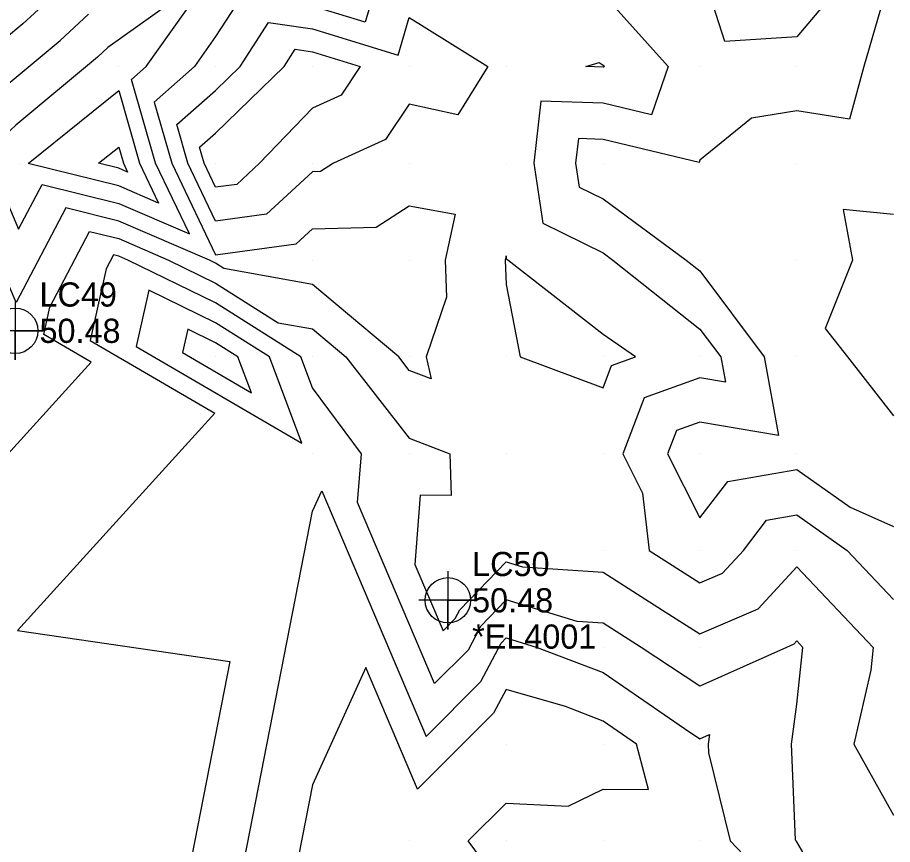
# Model space of a CAD drawing. Extents: x 2188792 to 2191981, y 386090 to 389710.
# Drawn here: x 2190119.7 to 2190210, y 387449.8 to 387535.2 of the extents above; entities that cross this region are included whole.
import ezdxf

# ---------------------------------------------------------------- set-up
doc = ezdxf.new("R2010")
doc.units = 0
for name, color, linetype in [('DTM Contours Major', 7, 'Continuous'), ('DTM Contours Minor', 7, 'Continuous'), ('Exist DTM QL2 LIDAR Elevation Point', 7, 'Continuous'), ('Exist DTM Regular Point Underwater CELL', 7, 'Continuous'), ('Exist DTM Regular Point Underwater Cogo Comment', 7, 'Continuous'), ('Exist DTM Regular Point Underwater Cogo Elevation', 7, 'Continuous'), ('Exist DTM Regular Point Underwater Cogo Number', 7, 'Continuous')]:
    doc.layers.add(name, color=color, linetype=linetype)

msp = doc.modelspace()

# ---------------------------------------------------------------- linework, layer by layer
at = {"layer": 'DTM Contours Major'}
for points in [[(2190120.784, 387520.144), (2190130.12, 387527.661), (2190132.267, 387520.154), (2190134.229, 387516.045), (2190130.12, 387517.817), (2190120.784, 387520.144)], [(2190210.127, 387514.854), (2190204.91, 387515.37), (2190205.884, 387510.153), (2190203.049, 387503.074), (2190205.351, 387500.152), (2190210.127, 387494.072)], [(2190140.121, 387503.672), (2190133.237, 387507.036), (2190131.936, 387501.22), (2190149.032, 387491.241), (2190145.675, 387500.152), (2190140.121, 387503.672)], [(2190141.057, 387437.7), (2190150.122, 387484.226), (2190151.078, 387486.326), (2190161.854, 387460.951), (2190167.508, 387466.609), (2190169.599, 387470.573)], [(2190169.599, 387470.573), (2190170.124, 387471.118), (2190173.327, 387470.149), (2190180.125, 387467.535), (2190188.52, 387461.754), (2190190.126, 387460.694), (2190191.113, 387461.136), (2190190.987, 387460.148), (2190191.023, 387459.251), (2190193.242, 387450.147), (2190200.127, 387442.935)]]:
    msp.add_lwpolyline(points, dxfattribs=at)
at = {"layer": 'DTM Contours Minor'}
for points in [[(2190157.179, 387540.156), (2190155.555, 387534.723), (2190150.122, 387536.394)], [(2190205.968, 387540.156), (2190200.127, 387533.215), (2190192.709, 387532.738), (2190190.326, 387540.156)], [(2190137.419, 387512.855), (2190133.935, 387520.154), (2190131.456, 387528.819), (2190132.964, 387530.155), (2190139.84, 387539.876), (2190128.988, 387532.121), (2190127.921, 387531.132), (2190119.493, 387524.101), (2190117.957, 387522.653), (2190117.61, 387520.473), (2190117.263, 387519.247), (2190119.789, 387513.362), (2190122.207, 387517.975), (2190130.12, 387516.003), (2190137.419, 387512.855)], [(2190209.867, 387539.896), (2190207.05, 387530.155), (2190205.562, 387524.719), (2190200.127, 387525.571), (2190195.461, 387524.82), (2190190.126, 387520.479), (2190190.042, 387520.238), (2190180.125, 387522.611), (2190177.575, 387522.703), (2190177.29, 387520.154), (2190177.666, 387517.695), (2190180.125, 387516.481), (2190188.704, 387510.153), (2190190.126, 387509.028), (2190196.764, 387500.152), (2190198.237, 387492.041), (2190190.126, 387493.426), (2190187.712, 387492.565), (2190186.79, 387490.151), (2190190.126, 387483.515), (2190193.006, 387487.271), (2190200.127, 387488.529), (2190205.652, 387484.625), (2190210.127, 387482.617)], [(2190125.03, 387538.995), (2190120.233, 387534.548), (2190118.327, 387532.958)], [(2190142.832, 387537.445), (2190140.121, 387533.244), (2190137.936, 387530.155), (2190133.791, 387526.483), (2190135.602, 387520.154), (2190140.121, 387510.688), (2190148.449, 387511.826), (2190150.122, 387513.372), (2190156.714, 387513.561), (2190160.123, 387515.743), (2190164.852, 387514.882), (2190163.811, 387510.153), (2190163.953, 387506.323), (2190161.854, 387500.152), (2190162.382, 387497.893), (2190160.123, 387498.751), (2190159.029, 387500.152), (2190150.122, 387507.648), (2190140.979, 387509.294), (2190140.121, 387509.839), (2190139.477, 387510.153), (2190130.12, 387514.189)], [(2190180.125, 387537.656), (2190186.856, 387530.155), (2190185.125, 387525.155), (2190180.125, 387526.351), (2190173.695, 387526.583), (2190172.976, 387520.154), (2190173.923, 387513.952), (2190180.125, 387510.891), (2190181.125, 387510.153), (2190190.126, 387503.025), (2190192.274, 387500.152), (2190192.751, 387497.527), (2190190.126, 387497.975), (2190184.359, 387495.918), (2190182.156, 387490.151), (2190184.21, 387486.066), (2190184.871, 387480.15), (2190190.126, 387476.811), (2190192.459, 387477.817), (2190194.614, 387480.15), (2190197.006, 387483.271), (2190200.127, 387483.822), (2190205.324, 387480.15), (2190210.127, 387475.104)], [(2190130.12, 387514.189), (2190124.661, 387515.549), (2190119.538, 387505.774), (2190114.185, 387518.245), (2190114.921, 387520.842), (2190115.656, 387525.462), (2190118.91, 387528.529), (2190124.077, 387532.84), (2190127.009, 387535.558)], [(2190137.27, 387520.154), (2190136.127, 387524.148), (2190140.121, 387527.686), (2190142.663, 387530.155), (2190145.589, 387534.688), (2190150.122, 387534.035), (2190158.962, 387531.315), (2190160.123, 387535.196), (2190168.231, 387530.155), (2190165.134, 387525.144), (2190160.123, 387526.252), (2190157.678, 387522.599), (2190152.287, 387520.154), (2190150.967, 387519.309), (2190150.122, 387519.285), (2190145.376, 387514.899), (2190140.121, 387514.181), (2190137.27, 387520.154)], [(2190138.937, 387520.154), (2190138.463, 387521.812), (2190140.121, 387523.281), (2190147.199, 387530.155), (2190148.345, 387531.932), (2190150.122, 387531.676), (2190155.065, 387530.155), (2190153.083, 387527.194), (2190150.122, 387525.851), (2190144.664, 387520.154), (2190142.303, 387517.972), (2190140.121, 387517.674), (2190138.937, 387520.154)], [(2190180.125, 387530.091), (2190178.363, 387530.155), (2190179.723, 387530.556), (2190180.125, 387530.28), (2190180.237, 387530.155), (2190180.208, 387530.071), (2190180.125, 387530.091)], [(2190128.032, 387520.152), (2190130.12, 387521.833), (2190130.6, 387520.154), (2190131.039, 387519.235), (2190130.12, 387519.632), (2190128.032, 387520.152)], [(2190102.656, 387472.478), (2190127.28, 387499.605), (2190122.378, 387502.466), (2190123.009, 387505.29), (2190127.115, 387513.123), (2190130.12, 387512.375), (2190135.271, 387510.153), (2190140.121, 387507.783), (2190146.592, 387503.682), (2190150.122, 387503.046), (2190153.561, 387500.152), (2190160.123, 387491.742), (2190164.315, 387490.151), (2190164.443, 387485.831), (2190161.246, 387485.884), (2190160.692, 387478.707), (2190163.602, 387471.856), (2190164.87, 387473.125), (2190165.339, 387474.015), (2190170.124, 387478.977), (2190171.805, 387478.469), (2190180.125, 387477.909), (2190186.275, 387474), (2190190.126, 387471.553), (2190196.133, 387474.143), (2190200.127, 387478.467), (2190208.01, 387470.149), (2190207.754, 387467.776), (2190206.02, 387460.148), (2190210.127, 387452.803)], [(2190205.919, 387440.147), (2190200.127, 387450.048), (2190200.031, 387450.147), (2190200.001, 387450.273), (2190199.597, 387460.148), (2190200.127, 387464.29), (2190200.757, 387470.149), (2190200.127, 387470.815), (2190199.807, 387470.469), (2190199.065, 387470.149), (2190190.126, 387466.15), (2190184.067, 387470.149), (2190180.125, 387472.655), (2190177.438, 387472.836), (2190170.124, 387475.048), (2190167.469, 387472.294), (2190166.189, 387469.867), (2190162.728, 387466.404), (2190154.788, 387485.099), (2190155.178, 387490.151), (2190150.122, 387496.958), (2190148.919, 387500.152), (2190140.121, 387505.728), (2190131.064, 387510.153), (2190130.12, 387510.56), (2190129.569, 387510.698), (2190128.816, 387509.261), (2190127.157, 387501.843), (2190140.037, 387494.325), (2190119.677, 387471.895), (2190141.586, 387468.701), (2190135.24, 387436.13)], [(2190181.006, 387499.27), (2190183.477, 387500.152), (2190180.125, 387502.478), (2190170.294, 387510.153), (2190170.18, 387510.209), (2190170.124, 387510.577), (2190170.03, 387510.153), (2190170.124, 387507.632), (2190171.571, 387500.152), (2190180.125, 387496.962), (2190181.006, 387499.27)], [(2190140.121, 387501.617), (2190137.257, 387503.016), (2190136.716, 387500.596), (2190143.828, 387496.445), (2190142.432, 387500.152), (2190140.121, 387501.617)], [(2190160.98, 387455.499), (2190155.643, 387468.068), (2190150.122, 387455.943), (2190146.873, 387439.27)], [(2190170.124, 387444.852), (2190166.204, 387450.147), (2190170.124, 387454.063), (2190176.528, 387453.744), (2190180.125, 387455.507), (2190184.816, 387455.457), (2190183.594, 387460.148), (2190180.125, 387462.537), (2190176.243, 387464.03), (2190170.124, 387465.81), (2190168.827, 387463.351), (2190160.98, 387455.499)]]:
    msp.add_lwpolyline(points, dxfattribs=at)
at = {"layer": 'Exist DTM QL2 LIDAR Elevation Point'}
for p, q in [((2190130.12, 387530.155), (2190130.12, 387530.155)), ((2190140.121, 387530.155), (2190140.121, 387530.155)), ((2190150.122, 387530.155), (2190150.122, 387530.155)), ((2190160.123, 387530.155), (2190160.123, 387530.155)), ((2190170.124, 387530.155), (2190170.124, 387530.155)), ((2190180.125, 387530.155), (2190180.125, 387530.155)), ((2190190.126, 387530.155), (2190190.126, 387530.155)), ((2190200.127, 387530.155), (2190200.127, 387530.155)), ((2190120.013, 387520.143), (2190120.013, 387520.143)), ((2190130.12, 387520.154), (2190130.12, 387520.154)), ((2190140.121, 387520.154), (2190140.121, 387520.154)), ((2190150.122, 387520.154), (2190150.122, 387520.154)), ((2190160.123, 387520.154), (2190160.123, 387520.154)), ((2190170.124, 387520.154), (2190170.124, 387520.154)), ((2190180.125, 387520.154), (2190180.125, 387520.154)), ((2190190.126, 387520.154), (2190190.126, 387520.154)), ((2190200.127, 387520.154), (2190200.127, 387520.154)), ((2190130.12, 387510.153), (2190130.12, 387510.153)), ((2190140.121, 387510.153), (2190140.121, 387510.153)), ((2190150.122, 387510.153), (2190150.122, 387510.153)), ((2190160.123, 387510.153), (2190160.123, 387510.153)), ((2190170.124, 387510.153), (2190170.124, 387510.153)), ((2190180.125, 387510.153), (2190180.125, 387510.153)), ((2190190.126, 387510.153), (2190190.126, 387510.153)), ((2190200.127, 387510.153), (2190200.127, 387510.153)), ((2190140.121, 387500.152), (2190140.121, 387500.152)), ((2190150.122, 387500.152), (2190150.122, 387500.152)), ((2190160.123, 387500.152), (2190160.123, 387500.152)), ((2190170.124, 387500.152), (2190170.124, 387500.152)), ((2190180.125, 387500.152), (2190180.125, 387500.152)), ((2190190.126, 387500.152), (2190190.126, 387500.152)), ((2190200.127, 387500.152), (2190200.127, 387500.152)), ((2190150.122, 387490.151), (2190150.122, 387490.151)), ((2190160.123, 387490.151), (2190160.123, 387490.151)), ((2190170.124, 387490.151), (2190170.124, 387490.151)), ((2190180.125, 387490.151), (2190180.125, 387490.151)), ((2190190.126, 387490.151), (2190190.126, 387490.151)), ((2190200.127, 387490.151), (2190200.127, 387490.151)), ((2190170.124, 387480.15), (2190170.124, 387480.15)), ((2190180.125, 387480.15), (2190180.125, 387480.15)), ((2190190.126, 387480.15), (2190190.126, 387480.15)), ((2190200.127, 387480.15), (2190200.127, 387480.15)), ((2190170.124, 387470.149), (2190170.124, 387470.149)), ((2190180.125, 387470.149), (2190180.125, 387470.149)), ((2190190.126, 387470.149), (2190190.126, 387470.149)), ((2190200.127, 387470.149), (2190200.127, 387470.149)), ((2190170.124, 387460.148), (2190170.124, 387460.148)), ((2190180.125, 387460.148), (2190180.125, 387460.148)), ((2190190.126, 387460.148), (2190190.126, 387460.148)), ((2190200.127, 387460.148), (2190200.127, 387460.148)), ((2190160.123, 387450.147), (2190160.123, 387450.147)), ((2190170.124, 387450.147), (2190170.124, 387450.147)), ((2190180.125, 387450.147), (2190180.125, 387450.147)), ((2190190.126, 387450.147), (2190190.126, 387450.147)), ((2190200.127, 387450.147), (2190200.127, 387450.147))]:
    msp.add_line(p, q, dxfattribs=at)
at = {"layer": 'Exist DTM Regular Point Underwater CELL'}
for points in [[(2190119.441, 387505.849), (2190119.441, 387499.849), (2190119.441, 387502.849), (2190122.441, 387502.849), (2190116.441, 387502.849)], [(2190164.107, 387478.01), (2190164.107, 387472.01), (2190164.107, 387475.01), (2190167.107, 387475.01), (2190161.107, 387475.01)]]:
    msp.add_lwpolyline(points, dxfattribs=at)
for centre in [(2190119.441, 387502.849), (2190164.107, 387475.01)]:
    msp.add_circle(centre, 2.344, dxfattribs=at)

# ---------------------------------------------------------------- texts
at = {"layer": 'Exist DTM Regular Point Underwater Cogo Comment'}
msp.add_text('*EL4001', height=2.5, dxfattribs=at).set_placement((2190166.607, 387470.01))
at = {"layer": 'Exist DTM Regular Point Underwater Cogo Elevation'}
for p in [(2190121.941, 387501.599), (2190166.607, 387473.76)]:
    msp.add_text('50.48', height=2.5, dxfattribs=at).set_placement(p)
at = {"layer": 'Exist DTM Regular Point Underwater Cogo Number'}
for s, p in [('LC49', (2190121.941, 387505.349)), ('LC50', (2190166.607, 387477.51))]:
    msp.add_text(s, height=2.5, dxfattribs=at).set_placement(p)

doc.saveas('drawing.dxf')
